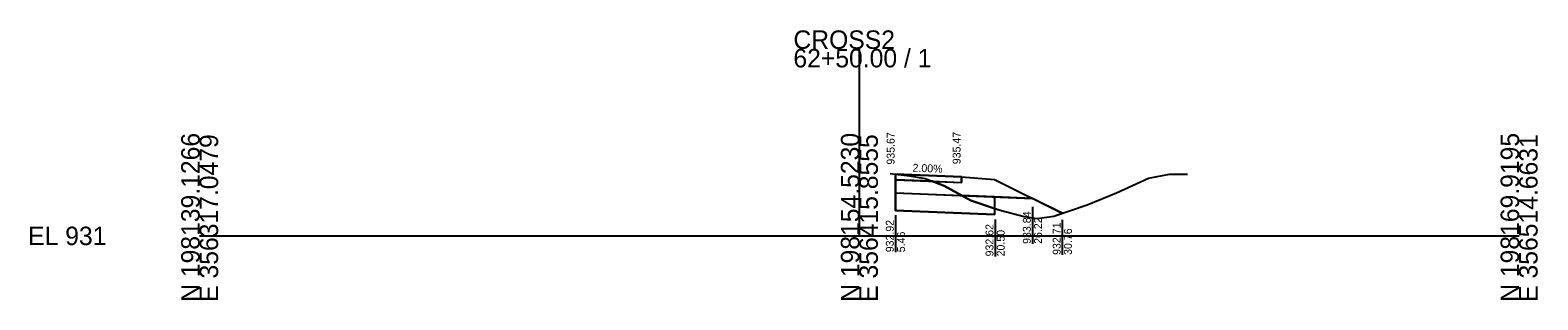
# Model space of a CAD drawing. Extents: x -26 to 203, y -10 to 14021.
# Drawn here: x -25.7 to 202.8, y 3490.3 to 3531.2 of the extents above; entities that cross this region are included whole.
import ezdxf

# ---------------------------------------------------------------- set-up
doc = ezdxf.new("R2010")
doc.units = 0
for name, color, linetype in [('Default', 7, 'Continuous'), ('P_E_XS_Ground', 7, 'Continuous'), ('P_XS', 7, 'Continuous'), ('P_XS_EAR_CommonGrnd', 7, 'Continuous'), ('P_XS_Lane', 7, 'Continuous'), ('P_XS_Rock', 7, 'Continuous')]:
    doc.layers.add(name, color=color, linetype=linetype)

msp = doc.modelspace()

# ---------------------------------------------------------------- linework, layer by layer
at = {"layer": 'Default'}
for p, q in [((100, 3500), (100, 3528.34)), ((0, 3500), (100, 3500)), ((100, 3500), (200, 3500))]:
    msp.add_line(p, q, dxfattribs=at)
at = {"layer": 'P_E_XS_Ground'}
for p, q in [((104.66, 3509.45), (107.6, 3509.09)), ((107.6, 3509.09), (109.95, 3508.7)), ((109.95, 3508.7), (112.84, 3507.61)), ((138.98, 3506.51), (143.83, 3508.73)), ((143.83, 3508.73), (147.03, 3509.36)), ((147.03, 3509.36), (149.74, 3509.37)), ((112.84, 3507.61), (116.89, 3505.36)), ((134.55, 3504.7), (138.98, 3506.51)), ((116.89, 3505.36), (121.34, 3503.89)), ((121.34, 3503.89), (124.96, 3502.93)), ((129.49, 3502.98), (134.55, 3504.7)), ((124.96, 3502.93), (126.96, 3502.65)), ((126.96, 3502.65), (129.49, 3502.98))]:
    msp.add_line(p, q, dxfattribs=at)
at = {"layer": 'P_XS'}
for p, q in [((105.46, 3509.35), (105.46, 3508.51)), ((105.46, 3508.51), (115.5, 3508.11)), ((105.46, 3506.51), (105.46, 3508.51)), ((115.5, 3508.95), (115.5, 3508.11)), ((105.46, 3506.51), (126.22, 3505.69)), ((105.46, 3506.51), (105.46, 3503.85)), ((120.5, 3505.91), (120.5, 3503.24)), ((105.46, 3503.85), (120.5, 3503.24))]:
    msp.add_line(p, q, dxfattribs=at)
at = {"layer": 'P_XS_EAR_CommonGrnd'}
for points in [[(107.6, 3509.09), (109.95, 3508.7), (111.03, 3508.29), (115.5, 3508.11), (115.5, 3508.95), (105.46, 3509.35)], [(107.6, 3509.09), (109.95, 3508.7), (111.03, 3508.29), (105.46, 3508.51), (105.46, 3509.35)], [(105.46, 3506.51), (115.53, 3506.11), (112.84, 3507.61), (111.03, 3508.29), (105.46, 3508.51)], [(120.5, 3508.55), (126.22, 3505.69), (120.5, 3505.91), (115.53, 3506.11), (112.84, 3507.61), (111.03, 3508.29), (115.5, 3508.11), (115.5, 3508.95)], [(105.46, 3506.51), (115.53, 3506.11), (116.89, 3505.36), (120.5, 3504.17), (120.5, 3503.24), (105.46, 3503.85)], [(120.5, 3505.91), (120.5, 3504.17), (116.89, 3505.36), (115.53, 3506.11)], [(124.96, 3502.93), (126.96, 3502.65), (129.49, 3502.98), (130.76, 3503.42), (126.22, 3505.69), (120.5, 3505.91), (120.5, 3504.17), (121.34, 3503.89)]]:
    msp.add_lwpolyline(points, close=True, dxfattribs=at)
at = {"layer": 'P_XS_Lane'}
for p, q in [((105.46, 3509.35), (115.5, 3508.95)), ((115.5, 3508.95), (120.5, 3508.55)), ((120.5, 3508.55), (130.76, 3503.42))]:
    msp.add_line(p, q, dxfattribs=at)
at = {"layer": 'P_XS_Rock'}
for p, q in [((126.23, 3504.39), (126.23, 3498.79)), ((105.46, 3503.14), (105.46, 3497.52)), ((120.57, 3502.49), (120.57, 3496.89)), ((130.76, 3502.41), (130.76, 3497.11))]:
    msp.add_line(p, q, dxfattribs=at)

# ---------------------------------------------------------------- texts
at = {"layer": 'Default'}
for s, p in [('CROSS2', (90, 3528.34)), ('62+50.00 / 1', (90, 3525.54)), ('EL 931', (-26, 3498.6))]:
    msp.add_text(s, height=2.8, dxfattribs=at).set_placement(p)
for s, p in [('N 198139.1266', (0, 3490)), ('E 356317.0479', (2.8, 3490)), ('N 198154.5230', (100, 3490)), ('E 356415.8555', (102.8, 3490)), ('N 198169.9195', (200, 3490)), ('E 356514.6631', (202.8, 3490))]:
    msp.add_text(s, height=2.8, rotation=90, dxfattribs=at).set_placement(p)
at = {"layer": 'P_XS_Rock'}
for s, rotation, p in [('935.67', 90, (105.34, 3510.8)), ('935.47', 90, (115.34, 3510.86)), ('2.00%', 357.7094, (108.04, 3509.74)), ('933.84', 90, (125.98, 3498.79)), ('932.92', 90, (105.21, 3497.52)), ('932.62', 90, (120.32, 3496.89)), ('26.22', 90, (127.68, 3498.79)), ('932.71', 90, (130.51, 3497.12)), ('5.46', 90, (106.91, 3497.52)), ('20.50', 90, (122.02, 3496.89)), ('30.76', 90, (132.21, 3497.12))]:
    msp.add_text(s, height=1.2, rotation=rotation, dxfattribs=at).set_placement(p)

doc.saveas('drawing.dxf')
